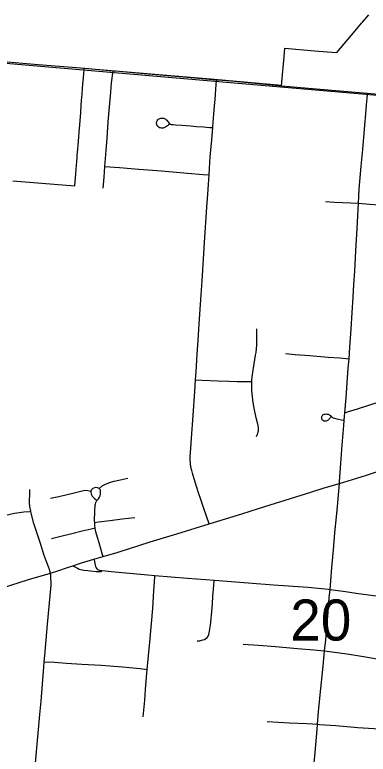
# Model space of a CAD drawing. Extents: x -1.4 to 35.4, y 0 to 22.
# Drawn here: x 19.136 to 19.497, y 17.179 to 17.934 of the extents above; entities that cross this region are included whole.
import ezdxf

# ---------------------------------------------------------------- set-up
doc = ezdxf.new("R2010")
doc.units = 0
for name, color, linetype in [('GM_X_City_Street', 7, 'Continuous'), ('GM_X_Corporation', 7, 'Continuous'), ('GM_X_County_Road', 7, 'Continuous'), ('GM_X_Section', 7, 'Continuous'), ('GM_X_Section_Text', 7, 'Continuous'), ('GM_X_Township_Road', 7, 'Continuous')]:
    doc.layers.add(name, color=color, linetype=linetype)

msp = doc.modelspace()

# ---------------------------------------------------------------- linework, layer by layer
at = {"layer": 'GM_X_City_Street'}
for points in [[(19.22657, 17.75687), (19.22743, 17.76818), (19.22825, 17.77905), (19.22949, 17.79544), (19.2305, 17.80814), (19.23182, 17.82478), (19.23307, 17.84015), (19.2343, 17.85508), (19.23514, 17.86437), (19.2366, 17.8768)], [(19.46759, 17.4558), (19.4677, 17.45769), (19.4689, 17.47622), (19.47031, 17.49504), (19.47126, 17.50651), (19.4719, 17.51469), (19.47231, 17.51993), (19.47267, 17.52447), (19.47299, 17.52769), (19.47431, 17.54307), (19.47582, 17.56353), (19.47653, 17.57326), (19.47725, 17.583), (19.47813, 17.59468), (19.4793, 17.61324), (19.48037, 17.63026), (19.48137, 17.64591), (19.48218, 17.65882), (19.48303, 17.67242), (19.48418, 17.69297), (19.48544, 17.71578), (19.48686, 17.74157), (19.48765, 17.75602), (19.4897, 17.77955), (19.4912, 17.79645), (19.4934, 17.82138), (19.49442, 17.83287), (19.49519, 17.84183), (19.49611, 17.85255), (19.49624, 17.85395)], [(19.2941, 17.8223), (19.2932, 17.82152), (19.29204, 17.82066), (19.29106, 17.82), (19.2902, 17.81946), (19.28933, 17.81897), (19.28851, 17.81864), (19.28769, 17.8184), (19.28681, 17.81832), (19.28596, 17.81827), (19.28495, 17.81843), (19.28407, 17.81873), (19.28324, 17.81918), (19.28243, 17.81984), (19.28192, 17.82048), (19.28144, 17.8214), (19.28117, 17.82217), (19.28107, 17.82316), (19.28109, 17.82402), (19.28127, 17.82501), (19.28166, 17.82579), (19.28226, 17.82666), (19.28281, 17.82725), (19.28362, 17.82781), (19.2844, 17.8282), (19.28526, 17.82847), (19.28623, 17.82855), (19.28711, 17.82855), (19.28808, 17.82832), (19.28892, 17.82806), (19.28981, 17.8276), (19.29076, 17.82685), (19.29151, 17.82625), (19.29221, 17.8255), (19.2927, 17.82486), (19.29369, 17.82352), (19.29422, 17.82284), (19.2952, 17.82223), (19.29603, 17.82209), (19.29798, 17.82193), (19.30019, 17.82175), (19.30679, 17.82126), (19.31562, 17.82056), (19.32181, 17.82005), (19.3289, 17.81946), (19.33487, 17.81897), (19.33847, 17.81904)], [(19.22825, 17.77905), (19.24315, 17.77807), (19.26301, 17.77645), (19.28607, 17.77456), (19.31255, 17.7724), (19.32868, 17.77108), (19.33466, 17.77074)], [(19.45314, 17.74328), (19.46245, 17.74276), (19.48686, 17.74157), (19.49798, 17.74066), (19.52248, 17.73903), (19.54002, 17.7378), (19.54554, 17.73743), (19.55706, 17.73659), (19.57513, 17.73526), (19.62686, 17.73084), (19.63414, 17.73022), (19.67238, 17.72677), (19.69834, 17.72418), (19.70098, 17.72387), (19.71008, 17.7232), (19.73387, 17.72144), (19.75233, 17.72006), (19.76783, 17.71891), (19.76992, 17.71877)], [(19.38308, 17.50366), (19.38391, 17.506), (19.38485, 17.50953), (19.38493, 17.51263), (19.38438, 17.51607), (19.38274, 17.52267), (19.38051, 17.53239), (19.37928, 17.54037), (19.37884, 17.54468), (19.37867, 17.54652), (19.37829, 17.55147), (19.37831, 17.55956), (19.37831, 17.56079), (19.37861, 17.56451), (19.37945, 17.57129), (19.38017, 17.57556), (19.38118, 17.58229), (19.38206, 17.58644), (19.38264, 17.58946), (19.38328, 17.5969), (19.38343, 17.60043), (19.3834, 17.60732), (19.38328, 17.61357)], [(19.41251, 17.58818), (19.42226, 17.58738), (19.43705, 17.58617), (19.45605, 17.58467), (19.46787, 17.58374), (19.47725, 17.583)], [(19.47299, 17.52769), (19.47585, 17.52865), (19.48577, 17.53196), (19.50817, 17.53903), (19.52587, 17.54461), (19.54326, 17.55004), (19.55187, 17.55265), (19.56064, 17.55531), (19.62614, 17.57474), (19.64813, 17.58139), (19.67628, 17.58924), (19.68207, 17.59025), (19.6851, 17.5905), (19.68822, 17.59064)], [(19.32077, 17.56139), (19.32735, 17.56101), (19.34345, 17.56025), (19.35475, 17.5599), (19.36326, 17.55963), (19.37478, 17.55958), (19.37831, 17.55956)], [(19.45879, 17.52384), (19.45838, 17.52315), (19.45793, 17.52249), (19.45743, 17.52187), (19.45702, 17.52134), (19.45661, 17.52084), (19.45603, 17.52031), (19.45538, 17.51982), (19.4548, 17.51949), (19.45398, 17.51928), (19.4532, 17.5192), (19.45201, 17.51932), (19.45115, 17.51965), (19.45028, 17.52031), (19.44983, 17.52101), (19.44958, 17.52162), (19.44941, 17.52252), (19.44946, 17.52323), (19.44958, 17.52397), (19.44987, 17.52471), (19.45049, 17.52544), (19.45106, 17.5259), (19.45176, 17.52623), (19.45246, 17.52643), (19.45328, 17.52656), (19.45415, 17.5266), (19.45513, 17.52648), (19.45587, 17.52627), (19.45671, 17.52599), (19.45735, 17.52557), (19.45821, 17.52505), (19.45908, 17.5243), (19.46011, 17.52348), (19.46125, 17.52274), (19.46233, 17.52236), (19.4647, 17.52171), (19.47139, 17.52014), (19.47231, 17.51993)], [(19.22245, 17.45067), (19.22566, 17.45322), (19.22837, 17.4547), (19.23125, 17.45601), (19.23396, 17.45692), (19.23767, 17.45788), (19.24257, 17.45914), (19.25159, 17.46101)], [(19.44014, 17.15302), (19.44272, 17.18103), (19.44471, 17.20453), (19.44515, 17.2099), (19.44624, 17.22309), (19.44857, 17.24654), (19.45082, 17.26912), (19.45239, 17.28488), (19.45351, 17.29618), (19.4547, 17.30816), (19.45593, 17.32422), (19.45705, 17.339), (19.45787, 17.3476), (19.45869, 17.35617), (19.45989, 17.37008), (19.46143, 17.38798), (19.46287, 17.40546), (19.46439, 17.42171), (19.46536, 17.43211), (19.46759, 17.4558)], [(19.15722, 17.16673), (19.16019, 17.20079), (19.16199, 17.21999), (19.16328, 17.23368), (19.16602, 17.2682), (19.16646, 17.27384), (19.16697, 17.28027), (19.16981, 17.31198), (19.17339, 17.3518), (19.1733, 17.36173), (19.17278, 17.36426), (19.17137, 17.36887), (19.16847, 17.37669), (19.16643, 17.3822), (19.16258, 17.39427), (19.1593, 17.40456), (19.15603, 17.41479), (19.15303, 17.42547), (19.15265, 17.42735), (19.15187, 17.43225), (19.15156, 17.4359), (19.15141, 17.43898), (19.15166, 17.44374), (19.15195, 17.44951)], [(19.17273, 17.44055), (19.18121, 17.44235), (19.19563, 17.44592), (19.20388, 17.44779), (19.20667, 17.44845), (19.20881, 17.4487), (19.21078, 17.44862), (19.2141, 17.44788)], [(19.2141, 17.44788), (19.2139, 17.44639), (19.21423, 17.44516), (19.21473, 17.44418), (19.21546, 17.44286), (19.21645, 17.44163), (19.21777, 17.44032), (19.219, 17.43916), (19.22022, 17.43817)], [(19.22245, 17.45067), (19.22065, 17.45133), (19.21925, 17.4515), (19.2176, 17.45117), (19.2162, 17.45059), (19.21514, 17.44969), (19.21448, 17.44886), (19.2141, 17.44788)], [(19.22022, 17.43817), (19.2218, 17.44015), (19.2227, 17.44155), (19.22344, 17.44319), (19.22385, 17.44492), (19.22401, 17.44697), (19.22385, 17.44845), (19.22344, 17.4496), (19.22245, 17.45067)], [(19.21792, 17.41582), (19.21782, 17.41763), (19.21809, 17.42727), (19.21852, 17.43383), (19.21877, 17.43499), (19.21917, 17.43621), (19.21951, 17.43692), (19.22022, 17.43817)], [(19.10679, 17.41699), (19.10967, 17.41782), (19.1274, 17.42317), (19.13162, 17.42427), (19.13628, 17.4253), (19.14078, 17.42613), (19.14561, 17.42678), (19.15153, 17.42724), (19.15265, 17.42735)], [(19.21792, 17.41582), (19.2219, 17.41641), (19.2337, 17.41792), (19.24591, 17.4195), (19.25884, 17.4211)], [(19.21834, 17.41032), (19.21809, 17.41247), (19.21792, 17.41582)], [(19.17375, 17.39939), (19.18205, 17.40144), (19.19476, 17.40459), (19.20521, 17.40719), (19.21421, 17.40934), (19.21834, 17.41032)], [(19.22657, 17.38112), (19.22603, 17.38293), (19.22244, 17.39504), (19.2208, 17.40056), (19.21907, 17.40639), (19.21842, 17.40968), (19.21834, 17.41032)], [(19.2172, 17.37834), (19.21735, 17.37761), (19.21812, 17.37414), (19.21879, 17.3711), (19.21953, 17.36944), (19.22007, 17.36865), (19.22083, 17.36804), (19.22181, 17.36757), (19.22288, 17.36719), (19.22473, 17.36679), (19.22557, 17.36672), (19.23474, 17.36586), (19.27217, 17.36237), (19.2793, 17.36179), (19.31262, 17.35912), (19.34001, 17.35692), (19.36141, 17.35521), (19.40042, 17.35208), (19.43552, 17.34973), (19.45587, 17.34788), (19.45787, 17.3476), (19.47127, 17.3457), (19.48688, 17.34348), (19.505, 17.3409)], [(19.1957, 17.37172), (19.19699, 17.37082), (19.20023, 17.36914), (19.20196, 17.36839), (19.20342, 17.36787), (19.20511, 17.3675), (19.20685, 17.36721), (19.21095, 17.3668), (19.21377, 17.3665), (19.21953, 17.36601), (19.22308, 17.36571), (19.2244, 17.36595), (19.22557, 17.36672)], [(19.26751, 17.21741), (19.26893, 17.23447), (19.26985, 17.24561), (19.27106, 17.26221), (19.27141, 17.26597), (19.27399, 17.29375), (19.27717, 17.32808), (19.2783, 17.34622), (19.27917, 17.36004), (19.2793, 17.36179)], [(19.32239, 17.29508), (19.32389, 17.29509), (19.32524, 17.29521), (19.32833, 17.29598), (19.32993, 17.29657), (19.33136, 17.29738), (19.33269, 17.29856), (19.33364, 17.29989), (19.33438, 17.30152), (19.33482, 17.3031), (19.33512, 17.30485), (19.33549, 17.30694), (19.336, 17.31104), (19.33629, 17.31403), (19.33734, 17.32508), (19.33791, 17.33294), (19.33847, 17.34062), (19.33912, 17.34771), (19.33985, 17.35584), (19.34001, 17.35692)], [(19.36941, 17.29178), (19.38505, 17.29054), (19.40218, 17.28919), (19.42466, 17.28742), (19.44141, 17.28589), (19.45239, 17.28488), (19.46522, 17.28306), (19.47742, 17.28137), (19.4901, 17.27933), (19.50789, 17.27628), (19.51391, 17.27524), (19.53997, 17.27098), (19.55505, 17.26851), (19.56845, 17.26631), (19.59296, 17.26318), (19.62197, 17.25822), (19.64458, 17.25436), (19.67169, 17.25017), (19.68905, 17.24749), (19.6958, 17.24616), (19.7009, 17.24466), (19.70372, 17.24336), (19.70662, 17.24141)], [(19.16646, 17.27384), (19.17697, 17.27317), (19.18916, 17.2724), (19.20477, 17.2714), (19.22459, 17.27014), (19.24628, 17.26858), (19.26422, 17.26704), (19.26665, 17.26668), (19.27141, 17.26597)], [(19.39393, 17.21263), (19.405, 17.21198), (19.41637, 17.21145), (19.43418, 17.2106), (19.44515, 17.2099), (19.44727, 17.20983), (19.46373, 17.20865), (19.4861, 17.20675), (19.5139, 17.20502), (19.5461, 17.20302), (19.55803, 17.20191), (19.56032, 17.20169), (19.57145, 17.20084), (19.59336, 17.19916), (19.63909, 17.1955), (19.6798, 17.19266)]]:
    msp.add_lwpolyline(points, dxfattribs=at)
at = {"layer": 'GM_X_Corporation'}
msp.add_lwpolyline([(19.13455, 17.76441), (19.1976, 17.75928), (19.19862, 17.77188), (19.19962, 17.78434), (19.19993, 17.78809), (19.20013, 17.79057), (19.20063, 17.7968), (19.20095, 17.80082), (19.20163, 17.80926), (19.20202, 17.8141), (19.20264, 17.82171), (19.20364, 17.83417), (19.2037, 17.8349), (19.20464, 17.84664), (19.20486, 17.84941), (19.20514, 17.85286), (19.20565, 17.85909), (19.20683, 17.87382), (19.20687, 17.87426), (19.20719, 17.87783), (19.20734, 17.87948), (19.21481, 17.87886), (19.33595, 17.86841), (19.40858, 17.86214), (19.40875, 17.86415), (19.40883, 17.86513), (19.41099, 17.89088), (19.41174, 17.89986), (19.44222, 17.8973), (19.45544, 17.89619), (19.45967, 17.89584), (19.46478, 17.89541), (19.48357, 17.9176), (19.48358, 17.91759), (19.49006, 17.92525), (19.49109, 17.92647), (19.49741, 17.93392)], dxfattribs=at)
at = {"layer": 'GM_X_County_Road'}
msp.add_line((19.20774, 17.87947), (19.2366, 17.8768), dxfattribs=at)
for points in [[(18.99566, 17.89691), (19.00185, 17.89638), (19.02106, 17.89479), (19.06193, 17.89141), (19.0768, 17.89017), (19.12078, 17.88673), (19.16039, 17.88318), (19.18642, 17.88102), (19.20774, 17.87947)], [(19.2366, 17.8768), (19.23916, 17.87657), (19.2645, 17.87433), (19.31643, 17.87006), (19.34208, 17.86767)], [(19.34208, 17.86767), (19.34361, 17.86753), (19.35724, 17.86638), (19.37061, 17.86508), (19.38862, 17.86332), (19.40885, 17.86135)], [(19.40885, 17.86135), (19.43214, 17.85937), (19.44769, 17.85814), (19.48801, 17.85469), (19.49624, 17.85395)], [(19.49624, 17.85395), (19.55274, 17.84889), (19.5656, 17.84763)], [(19.46759, 17.4558), (19.48508, 17.46106), (19.49509, 17.46418), (19.5146, 17.4706)], [(19.33451, 17.41452), (19.36786, 17.42469), (19.38497, 17.4302), (19.39676, 17.43384), (19.43825, 17.44672), (19.45182, 17.45107), (19.46759, 17.4558)], [(19.22657, 17.38112), (19.24179, 17.38562), (19.27435, 17.39597), (19.30169, 17.40424), (19.33451, 17.41452)], [(19.1957, 17.37172), (19.20431, 17.37453), (19.2172, 17.37834), (19.22657, 17.38112)], [(19.17278, 17.36426), (19.18023, 17.36654), (19.19019, 17.36993), (19.1957, 17.37172)], [(18.80892, 17.25115), (18.81161, 17.25208), (18.84002, 17.26185), (18.86648, 17.27013), (18.8906, 17.27786), (18.9417, 17.29341), (18.96323, 17.29991), (18.99158, 17.30847), (19.0205, 17.31774), (19.04176, 17.32465), (19.0952, 17.34077), (19.12279, 17.34901), (19.15046, 17.35753), (19.17278, 17.36426)]]:
    msp.add_lwpolyline(points, dxfattribs=at)
at = {"layer": 'GM_X_Section'}
msp.add_lwpolyline([(20.00335, 17.80912), (19.91613, 16.79977), (18.89767, 16.8845), (18.98115, 17.8973)], close=True, dxfattribs=at)
at = {"layer": 'GM_X_Township_Road'}
for points in [[(19.33847, 17.81904), (19.33889, 17.82487), (19.33915, 17.82841), (19.33946, 17.83266), (19.34025, 17.84118), (19.3407, 17.84739), (19.34147, 17.85796), (19.34203, 17.86702), (19.34208, 17.86767)], [(19.33466, 17.77074), (19.33501, 17.77717), (19.33567, 17.78924), (19.33692, 17.80258), (19.33764, 17.81027), (19.33847, 17.81904)], [(19.32077, 17.56139), (19.32132, 17.56948), (19.32254, 17.5875), (19.32334, 17.60169), (19.32429, 17.61851), (19.32616, 17.64329), (19.32738, 17.66236), (19.32983, 17.70166), (19.3322, 17.73757), (19.33317, 17.75102), (19.3339, 17.76112), (19.33466, 17.77074)], [(19.33451, 17.41452), (19.32922, 17.4301), (19.32609, 17.43932), (19.32376, 17.4462), (19.32054, 17.45685), (19.31776, 17.46606), (19.3169, 17.46889), (19.31603, 17.47235), (19.31554, 17.47605), (19.31529, 17.47987), (19.31542, 17.48271), (19.31604, 17.49185), (19.31673, 17.50198), (19.3183, 17.52499), (19.31997, 17.54942), (19.32077, 17.56139)]]:
    msp.add_lwpolyline(points, dxfattribs=at)

# ---------------------------------------------------------------- texts
at = {"layer": 'GM_X_Section_Text'}
msp.add_text('20', height=0.041856, rotation=0.00001, dxfattribs=at).set_placement((19.41736, 17.29541))

doc.saveas('drawing.dxf')
